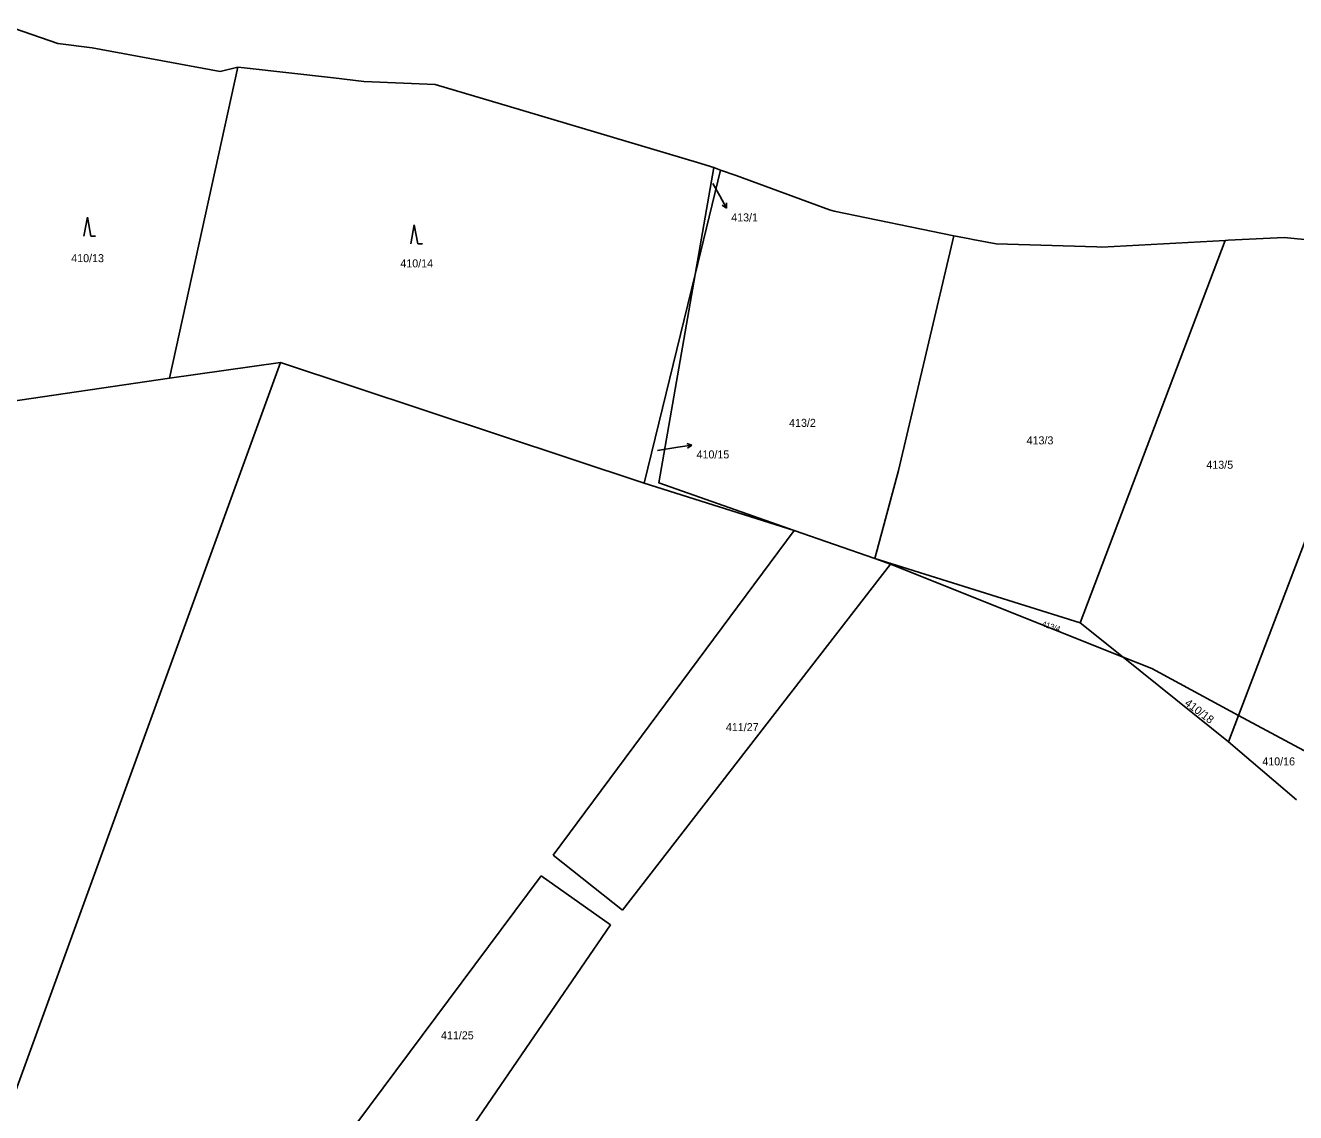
# Model space of a CAD drawing. Extents: x -744566 to -741843, y -1128407 to -1126744.
# Drawn here: x -743925.6 to -743655.8, y -1127042.4 to -1126811.4 of the extents above; entities that cross this region are included whole.
import ezdxf

# ---------------------------------------------------------------- set-up
doc = ezdxf.new("R2010")
doc.units = 0
for name, color, linetype in [('Hranice parcel', 7, 'Continuous'), ('Parcelní čísla', 7, 'Continuous'), ('Pop  PČ popisy', 7, 'Continuous'), ('Značky kultur', 7, 'Continuous')]:
    doc.layers.add(name, color=color, linetype=linetype)

msp = doc.modelspace()

# ---------------------------------------------------------------- linework, layer by layer
at = {"layer": 'Hranice parcel'}
for p, q in [((-743895.01, -1126886.33), (-743880.51, -1126820.27)), ((-743884.23, -1126821.23), (-743880.51, -1126820.27)), ((-743860.17, -1126822.58), (-743853.7, -1126823.31)), ((-743783.35, -1126864.33), (-743779.39, -1126841.61)), ((-743779.39, -1126841.61), (-743777.93, -1126842.14)), ((-743783.35, -1126864.33), (-743777.93, -1126842.14)), ((-743777.93, -1126842.14), (-743774.65, -1126843.34)), ((-743701.53, -1126938.34), (-743670.72, -1126857.13)), ((-743667.9, -1126958), (-743630.32, -1126859.26)), ((-743794.19, -1126908.65), (-743783.35, -1126864.33)), ((-743871.44, -1126883.01), (-743895.01, -1126886.33)), ((-743871.44, -1126883.01), (-743794.19, -1126908.65)), ((-743895.01, -1126886.33), (-743948.2, -1126894.15)), ((-743794.19, -1126908.65), (-743762.33, -1126918.74)), ((-743813.51, -1126987.67), (-743762.33, -1126918.74)), ((-743762.33, -1126918.74), (-743745.19, -1126924.71)), ((-743745.19, -1126924.71), (-743701.53, -1126938.34)), ((-743745.19, -1126924.71), (-743741.88, -1126925.86)), ((-743741.88, -1126925.86), (-743798.75, -1126999.39)), ((-743692.45, -1126945.62), (-743741.88, -1126925.86)), ((-743692.45, -1126945.62), (-743701.53, -1126938.34)), ((-743670.03, -1126963.61), (-743692.45, -1126945.62)), ((-743667.9, -1126958), (-743670.03, -1126963.61)), ((-743652.05, -1126966.54), (-743667.9, -1126958)), ((-743670.03, -1126963.61), (-743655.57, -1126975.98)), ((-743798.75, -1126999.39), (-743813.51, -1126987.67)), ((-743864.42, -1127056.89), (-743816.04, -1126992.08)), ((-743816.04, -1126992.08), (-743801.36, -1127002.53)), ((-743801.36, -1127002.53), (-743844.13, -1127064.95))]:
    msp.add_line(p, q, dxfattribs=at)
for points in [[(-743929.77, -1126811.42), (-743918.76, -1126815.23), (-743911.47, -1126816.19), (-743884.23, -1126821.23)], [(-743880.51, -1126820.27), (-743879.18, -1126820.45), (-743860.17, -1126822.58)], [(-743853.7, -1126823.31), (-743838.6, -1126823.96), (-743822.57, -1126828.73), (-743782.88, -1126840.57), (-743779.39, -1126841.61)], [(-743774.65, -1126843.34), (-743754.79, -1126850.58), (-743753.84, -1126850.92), (-743728.36, -1126856.1)], [(-743745.19, -1126924.71), (-743740.13, -1126905.97), (-743728.36, -1126856.1)], [(-743728.36, -1126856.1), (-743725.02, -1126856.78), (-743724.34, -1126856.92), (-743719.42, -1126857.82), (-743698.04, -1126858.47), (-743696.98, -1126858.5), (-743670.72, -1126857.13)], [(-743670.72, -1126857.13), (-743670.09, -1126857.07), (-743658.2, -1126856.48), (-743630.32, -1126859.26)], [(-743762.33, -1126918.74), (-743791.08, -1126908.6), (-743783.35, -1126864.33)], [(-743980.2, -1127091.58), (-743945.34, -1127086.24), (-743871.44, -1126883.01)], [(-743667.9, -1126958), (-743686.33, -1126948.07), (-743692.45, -1126945.62)]]:
    msp.add_lwpolyline(points, dxfattribs=at)
at = {"layer": 'Pop  PČ popisy'}
for p, q in [((-743779.56, -1126844.99), (-743778.13, -1126847.6)), ((-743778.13, -1126847.6), (-743776.675, -1126850.225)), ((-743776.675, -1126850.225), (-743777.599, -1126849.592)), ((-743776.675, -1126850.225), (-743776.723, -1126849.106)), ((-743791.37, -1126901.72), (-743787.01, -1126901.04)), ((-743787.01, -1126901.04), (-743784.046, -1126900.571)), ((-743784.046, -1126900.571), (-743785.113, -1126900.233)), ((-743784.046, -1126900.571), (-743784.957, -1126901.222))]:
    msp.add_line(p, q, dxfattribs=at)
at = {"layer": 'Značky kultur'}
for p, q in [((-743912.46, -1126852.17), (-743913.21, -1126856.17)), ((-743911.71, -1126856.17), (-743912.46, -1126852.17)), ((-743843.03, -1126853.81), (-743843.78, -1126857.81)), ((-743842.28, -1126857.81), (-743843.03, -1126853.81)), ((-743911.71, -1126856.17), (-743910.714, -1126856.17)), ((-743842.28, -1126857.81), (-743841.284, -1126857.81))]:
    msp.add_line(p, q, dxfattribs=at)

# ---------------------------------------------------------------- texts
at = {"layer": 'Parcelní čísla'}
for s, p in [('413/1', (-743775.69, -1126853.063)), ('410/13', (-743915.89, -1126861.72)), ('410/14', (-743845.97, -1126862.83)), ('413/2', (-743763.39, -1126896.71)), ('413/3', (-743712.94, -1126900.43)), ('410/15', (-743783.05, -1126903.413)), ('413/5', (-743674.75, -1126905.61)), ('411/27', (-743776.815, -1126961.35)), ('410/16', (-743662.87, -1126968.63)), ('411/25', (-743837.345, -1127026.83))]:
    msp.add_text(s, height=1.7, dxfattribs=at).set_placement(p)
for s, height, rotation, p in [('413/4', 1.19, 342, (-743709.793, -1126939.035)), ('410/18', 1.7, 323, (-743679.511, -1126955.698))]:
    msp.add_text(s, height=height, rotation=rotation, dxfattribs=at).set_placement(p)

doc.saveas('drawing.dxf')
